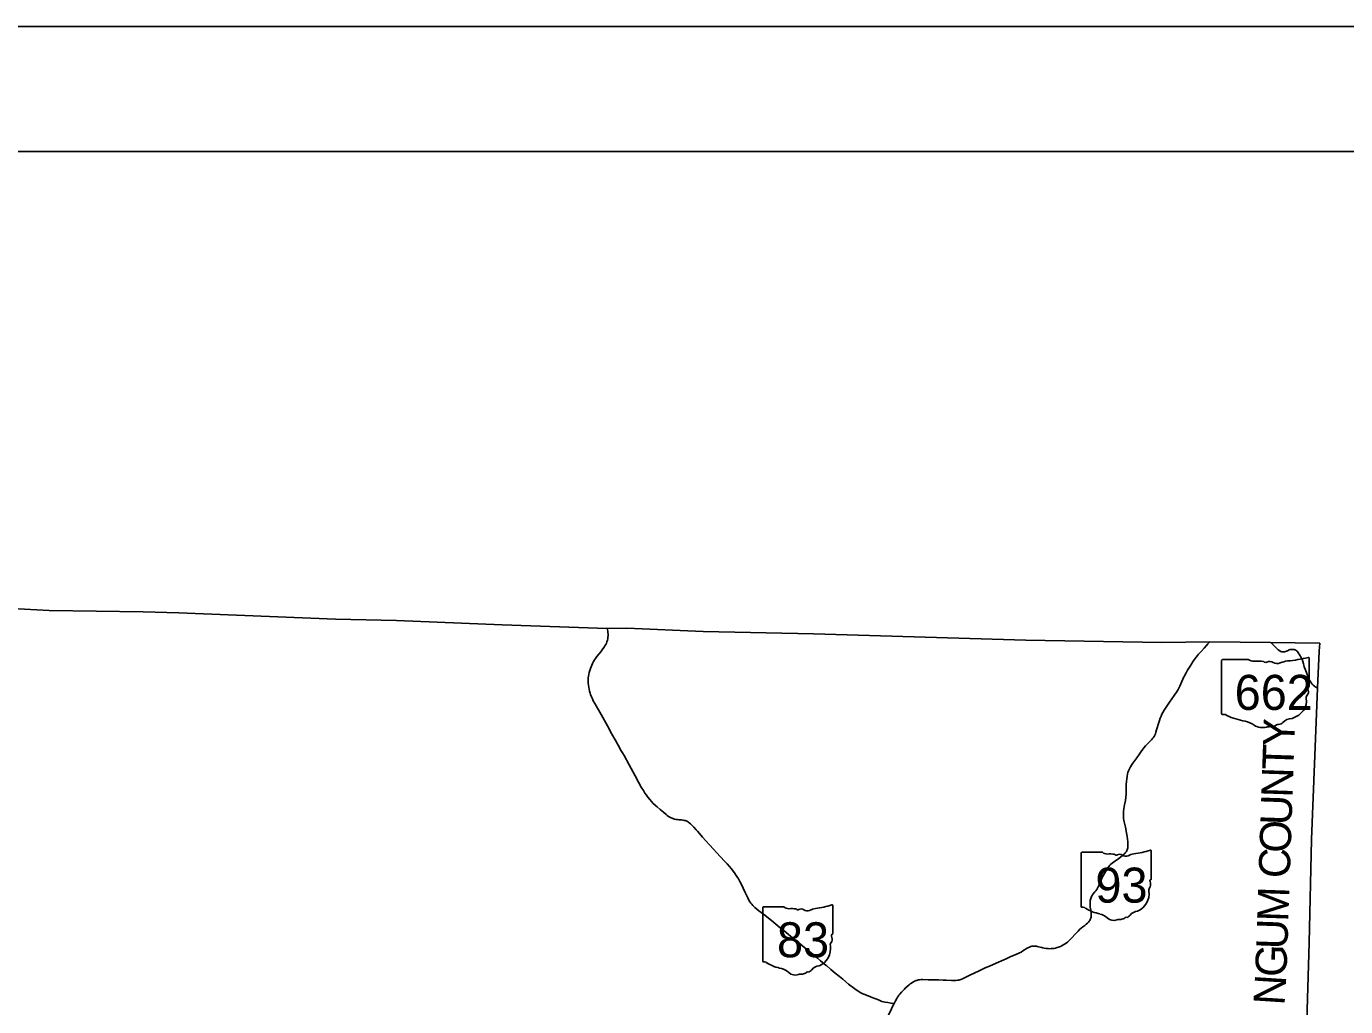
# Model space of a CAD drawing. Extents: x 2015843 to 2287843, y 623733 to 799733.
# Drawn here: x 2161112 to 2203322, y 768366 to 799733 of the extents above; entities that cross this region are included whole.
import ezdxf

# ---------------------------------------------------------------- set-up
doc = ezdxf.new("R2010")
doc.units = 0
for name, color, linetype in [('GM_X_County', 7, 'Continuous'), ('GM_X_County_Text', 7, 'Continuous'), ('GM_X_State_Location', 7, 'Continuous'), ('GM_X_State_Route', 7, 'Continuous'), ('GM_X_State_Shield', 7, 'Continuous'), ('SH_Border', 7, 'Continuous'), ('SH_Cut_Line', 7, 'Continuous')]:
    doc.layers.add(name, color=color, linetype=linetype)

msp = doc.modelspace()

# ---------------------------------------------------------------- linework, layer by layer
at = {"layer": 'GM_X_County'}
msp.add_lwpolyline([(2160255, 781127), (2161838, 781046), (2164851, 780995), (2165985, 780969), (2171000, 780768), (2172957, 780727), (2176338, 780588), (2179692, 780466), (2180329, 780472), (2182770, 780366), (2186293, 780295), (2193090, 780093), (2197442, 780016), (2198976, 780038), (2200924, 780017), (2202494, 779994), (2202479, 779737), (2202424, 778558), (2202231, 773716), (2202153, 770412), (2201913, 762197)], dxfattribs=at)
at = {"layer": 'GM_X_State_Route'}
for points in [[(2188873, 768462), (2188775, 768480), (2188678, 768496), (2188586, 768511), (2188581, 768512), (2188534, 768522), (2188487, 768535), (2188440, 768551), (2188395, 768569), (2188320, 768602), (2188254, 768630), (2188229, 768641), (2188122, 768683), (2187938, 768750), (2187877, 768775), (2187833, 768796), (2187790, 768820), (2187748, 768845), (2187694, 768881), (2187615, 768940), (2187421, 769090), (2187230, 769244), (2187128, 769327), (2186989, 769441), (2186851, 769558), (2186708, 769679), (2186701, 769685), (2186524, 769832), (2186423, 769915), (2186220, 770082), (2186016, 770247), (2185825, 770402), (2185649, 770549), (2185560, 770622), (2185484, 770684), (2185357, 770787), (2185229, 770891), (2185089, 771005), (2184950, 771119), (2184694, 771324), (2184552, 771435), (2184423, 771536), (2184387, 771569), (2184353, 771604), (2184321, 771641), (2184291, 771680), (2184264, 771721), (2184231, 771777), (2184192, 771849), (2184099, 772041), (2184042, 772159), (2183979, 772292), (2183941, 772365), (2183892, 772451), (2183841, 772535), (2183804, 772590), (2183765, 772643), (2183657, 772787), (2183606, 772852), (2183532, 772935), (2183450, 773024), (2183325, 773162), (2183194, 773303), (2183102, 773402), (2182973, 773544), (2182852, 773676), (2182750, 773792), (2182647, 773906), (2182582, 773978), (2182541, 774024), (2182464, 774106), (2182400, 774176), (2182364, 774212), (2182323, 774247), (2182292, 774272), (2182266, 774287), (2182240, 774300), (2182219, 774309), (2182190, 774319), (2182159, 774327), (2182119, 774334), (2182071, 774339), (2181993, 774346), (2181945, 774350), (2181897, 774357), (2181849, 774368), (2181818, 774378), (2181772, 774394), (2181742, 774407), (2181699, 774429), (2181657, 774454), (2181617, 774482), (2181579, 774513), (2181492, 774588), (2181391, 774672), (2181291, 774756), (2181240, 774802), (2181230, 774811), (2181171, 774867), (2181115, 774927), (2181061, 774989), (2181000, 775065), (2180951, 775131), (2180905, 775198), (2180852, 775281), (2180785, 775393), (2180697, 775550), (2180588, 775752), (2180465, 775983), (2180403, 776098), (2180237, 776398), (2180185, 776486), (2180145, 776554), (2180047, 776734), (2179951, 776904), (2179805, 777161), (2179801, 777168), (2179701, 777350), (2179498, 777716), (2179300, 778070), (2179252, 778156), (2179223, 778216), (2179196, 778276), (2179165, 778350), (2179150, 778397), (2179132, 778459), (2179116, 778523), (2179105, 778587), (2179097, 778652), (2179091, 778717), (2179088, 778783), (2179089, 778821), (2179092, 778884), (2179098, 778945), (2179107, 778994), (2179121, 779057), (2179138, 779121), (2179158, 779183), (2179181, 779244), (2179200, 779289), (2179229, 779348), (2179260, 779406), (2179293, 779462), (2179320, 779503), (2179368, 779569), (2179490, 779723), (2179560, 779814), (2179598, 779868), (2179625, 779909), (2179650, 779952), (2179671, 779997), (2179689, 780043), (2179702, 780091), (2179712, 780139), (2179719, 780188), (2179722, 780238), (2179722, 780287), (2179718, 780336), (2179714, 780382), (2179707, 780418), (2179693, 780463)], [(2188873, 768462), (2188923, 768551), (2188962, 768623), (2188986, 768666), (2189012, 768708), (2189031, 768735), (2189048, 768758), (2189056, 768767), (2189117, 768834), (2189184, 768906), (2189203, 768925), (2189231, 768953), (2189291, 769009), (2189353, 769063), (2189392, 769094), (2189432, 769122), (2189474, 769148), (2189517, 769173), (2189547, 769187), (2189578, 769199), (2189602, 769207), (2189625, 769214), (2189657, 769221), (2189690, 769226), (2189739, 769230), (2189789, 769231), (2189969, 769227), (2190117, 769224), (2190232, 769223), (2190298, 769222), (2190445, 769215), (2190543, 769211), (2190707, 769205), (2190805, 769203), (2190854, 769205), (2190903, 769209), (2190951, 769216), (2190983, 769224), (2191014, 769234), (2191059, 769252), (2191133, 769287), (2191294, 769369), (2191456, 769448), (2191575, 769503), (2191768, 769593), (2191949, 769672), (2192219, 769791), (2192309, 769831), (2192459, 769898), (2192482, 769908), (2192593, 769958), (2192774, 770037), (2192849, 770070), (2192893, 770090), (2192936, 770113), (2192993, 770146), (2193132, 770233), (2193176, 770258), (2193203, 770270), (2193226, 770279), (2193253, 770289), (2193284, 770296), (2193313, 770301), (2193331, 770303), (2193351, 770304), (2193385, 770304), (2193411, 770302), (2193432, 770299), (2193454, 770295), (2193499, 770283), (2193600, 770254), (2193630, 770248), (2193677, 770237), (2193737, 770228), (2193802, 770222), (2193851, 770220), (2193905, 770221), (2193946, 770223), (2193997, 770230), (2194044, 770240), (2194092, 770253), (2194138, 770269), (2194198, 770294), (2194242, 770314), (2194285, 770339), (2194331, 770367), (2194381, 770400), (2194419, 770430), (2194456, 770462), (2194492, 770495), (2194550, 770554), (2194682, 770700), (2194761, 770783), (2194820, 770840), (2194858, 770873), (2194909, 770914), (2194974, 770964), (2195021, 771004), (2195060, 771038), (2195092, 771071), (2195116, 771099), (2195134, 771123), (2195151, 771151), (2195162, 771175), (2195169, 771195), (2195179, 771226), (2195183, 771257), (2195185, 771286), (2195185, 771310), (2195183, 771342), (2195179, 771378), (2195166, 771453), (2195152, 771550), (2195148, 771599), (2195145, 771664), (2195147, 771713), (2195153, 771763), (2195159, 771795), (2195168, 771827), (2195179, 771858), (2195192, 771888), (2195208, 771917), (2195227, 771946), (2195248, 771974), (2195298, 772037), (2195328, 772074), (2195357, 772114), (2195383, 772156), (2195405, 772199), (2195425, 772244), (2195461, 772335), (2195485, 772392), (2195508, 772441), (2195537, 772499), (2195577, 772571), (2195682, 772757), (2195706, 772799), (2195724, 772826), (2195745, 772853), (2195777, 772890), (2195812, 772924), (2195852, 772957), (2195932, 773014), (2196064, 773111), (2196184, 773198), (2196220, 773229), (2196245, 773252), (2196267, 773275), (2196283, 773293), (2196293, 773307), (2196306, 773328), (2196320, 773357), (2196332, 773386), (2196342, 773417), (2196349, 773449), (2196353, 773481), (2196356, 773529), (2196356, 773578), (2196353, 773644), (2196345, 773725), (2196333, 773805), (2196316, 773913), (2196302, 773993), (2196277, 774105), (2196232, 774283), (2196224, 774330), (2196217, 774379), (2196212, 774429), (2196212, 774480), (2196212, 774543), (2196217, 774611), (2196230, 774692), (2196252, 774821), (2196278, 774966), (2196283, 775000), (2196287, 775030), (2196294, 775089), (2196298, 775146), (2196300, 775225), (2196305, 775469), (2196314, 775569), (2196322, 775650), (2196330, 775725), (2196346, 775816), (2196359, 775862), (2196372, 775910), (2196392, 775956), (2196414, 776001), (2196439, 776044), (2196469, 776090), (2196514, 776152), (2196640, 776323), (2196716, 776430), (2196781, 776525), (2196838, 776605), (2196877, 776658), (2196919, 776708), (2196953, 776744), (2197036, 776827), (2197083, 776871), (2197116, 776907), (2197136, 776932), (2197165, 776971), (2197192, 777013), (2197215, 777057), (2197235, 777100), (2197252, 777145), (2197276, 777224), (2197345, 777460), (2197366, 777523), (2197393, 777600), (2197416, 777660), (2197445, 777722), (2197474, 777779), (2197517, 777850), (2197562, 777921), (2197690, 778111), (2197839, 778325), (2197930, 778461), (2197964, 778517), (2197989, 778560), (2198016, 778618), (2198050, 778694), (2198083, 778769), (2198116, 778844), (2198149, 778917), (2198173, 778966), (2198188, 778994), (2198219, 779048), (2198264, 779128), (2198344, 779259), (2198397, 779344), (2198423, 779385), (2198477, 779466), (2198535, 779546), (2198578, 779599), (2198619, 779649), (2198696, 779732), (2198797, 779841), (2198871, 779924), (2198917, 779974), (2198977, 780035)], [(2202425, 778555), (2202388, 778576), (2202348, 778603), (2202322, 778624), (2202285, 778656), (2202255, 778689), (2202223, 778728), (2202194, 778766), (2202168, 778808), (2202147, 778848), (2202128, 778893), (2202066, 779059), (2202028, 779163), (2202000, 779241), (2201985, 779292), (2201974, 779337), (2201955, 779413), (2201947, 779441), (2201939, 779461), (2201924, 779492), (2201909, 779521), (2201835, 779648), (2201809, 779689), (2201790, 779716), (2201779, 779729), (2201767, 779741), (2201755, 779752), (2201742, 779762), (2201727, 779771), (2201713, 779778), (2201697, 779785), (2201681, 779790), (2201665, 779794), (2201649, 779797), (2201633, 779798), (2201614, 779799), (2201599, 779798), (2201583, 779797), (2201567, 779795), (2201544, 779789), (2201517, 779781), (2201458, 779756), (2201427, 779743), (2201396, 779731), (2201368, 779724), (2201351, 779720), (2201336, 779718), (2201320, 779717), (2201304, 779718), (2201288, 779720), (2201273, 779723), (2201258, 779728), (2201244, 779733), (2201230, 779740), (2201215, 779748), (2201199, 779758), (2201180, 779774), (2201163, 779787), (2200925, 780014)], [(2188669, 768052), (2188682, 768076), (2188793, 768292), (2188847, 768408), (2188873, 768462)]]:
    msp.add_lwpolyline(points, dxfattribs=at)
at = {"layer": 'GM_X_State_Shield'}
for p, q in [((2199356, 779442), (2199356, 777741)), ((2200204, 779471), (2199383, 779471)), ((2202158, 778624), (2202158, 779514)), ((2202157, 778624), (2202158, 778624)), ((2195539, 773304), (2194883, 773304)), ((2197102, 772456), (2197102, 773346)), ((2194861, 773275), (2194861, 771573)), ((2197102, 772456), (2197102, 772456)), ((2186914, 770707), (2186914, 771597)), ((2184672, 771526), (2184672, 769824)), ((2185351, 771555), (2184694, 771555)), ((2186913, 770707), (2186914, 770707))]:
    msp.add_line(p, q, dxfattribs=at)
for centre, radius, start, end in [((2194887, 773278), 26, 98.1301, 188.1301), ((2195696, 773501), 252, 231.6195, 271.1119), ((2196304, 775623), 2377, 275.8445, 288.9065), ((2197077, 773350), 25, 351.8621, 97.738), ((2195779, 772349), 904, 80.4867, 94.9883), ((2195985, 773287), 72.7, 219.7921, 297.1024), ((2196091, 773090), 151, 54.4667, 119.1411), ((2196286, 773360), 182, 233.8562, 294.8282), ((2196607, 772784), 478, 97.3462, 120.7689), ((2197076, 772453), 26.7, 289.6038, 7.7341), ((2196437, 771971), 595, 292.3089, 8.9858), ((2197192, 772084), 169, 136.8065, 186.9296), ((2197097, 772391), 38.6, 107.944, 210.337), ((2196851, 772278), 232, 340.033, 23.6496), ((2186115, 773874), 2377, 275.8445, 288.9065), ((2186889, 771601), 25, 351.8621, 97.738), ((2184698, 771529), 26, 98.1301, 188.1301), ((2185507, 771752), 252, 231.6195, 271.1119), ((2185590, 770600), 904, 80.4867, 94.9883), ((2185796, 771538), 72.7, 219.7921, 297.1024), ((2185902, 771341), 151, 54.4667, 119.1411), ((2186097, 771611), 182, 233.8562, 294.8282), ((2186418, 771035), 478, 97.3462, 120.7689), ((2194887, 771570), 26.2, 171.9584, 258.3066), ((2194891, 771744), 200, 267.339, 280.6039), ((2194932, 771475), 72.1, 29.7484, 93.2717), ((2195842, 773004), 1716, 240.4129, 257.1985), ((2195330, 770809), 537, 47.1842, 75.836), ((2195911, 771467), 341, 230.7004, 286.2918), ((2196133, 771339), 182, 268.777, 315.5493), ((2196297, 771175), 51.1, 65.7517, 132.6484), ((2196275, 771409), 192, 282.8732, 323.2771), ((2196688, 771096), 326, 94.4031, 142.5768), ((2196108, 770879), 280, 85.6951, 111.2099), ((2187003, 770335), 169, 136.8065, 186.9296), ((2186908, 770642), 38.6, 107.944, 210.337), ((2186662, 770529), 232, 340.033, 23.6496), ((2186887, 770704), 26.7, 289.6038, 7.7341), ((2186248, 770222), 595, 292.3089, 8.9858), ((2184698, 769821), 26.2, 171.9584, 258.3066), ((2184702, 769995), 200, 267.339, 280.6039), ((2184743, 769726), 72.1, 29.7484, 93.2717), ((2185653, 771255), 1716, 240.4129, 257.1985), ((2185141, 769060), 537, 47.1842, 75.836), ((2186086, 769660), 192, 282.8732, 323.2771), ((2186499, 769347), 326, 94.4031, 142.5768), ((2185722, 769718), 341, 230.7004, 286.2918), ((2185919, 769130), 280, 85.6951, 111.2099), ((2185944, 769590), 182, 268.777, 315.5493), ((2186108, 769426), 51.1, 65.7517, 132.6484)]:
    msp.add_arc(centre, radius, start, end, dxfattribs=at)
for centre, major_axis, start_param, end_param in [((2199388, 779446), (32.5, 0), 1.712693, 3.28349), ((2200399, 779669), (315, 0), 4.042523, 4.731795), ((2200504, 778516), (1130, 0), 1.404758, 1.657858), ((2200760, 779455), (90.8, 0), 3.836095, 5.185415), ((2200894, 779258), (189, 0), 0.950623, 2.079405), ((2201137, 779528), (227, 0), 4.081561, 5.145723), ((2201539, 778952), (598, 0), 1.699011, 2.107814), ((2201160, 781791), (2971, 0), 4.814394, 5.042369), ((2202126, 779517), (31.2, 0), 6.141152, 7.989035), ((2202269, 778251), (211, 0), 2.387724, 3.262537), ((2202150, 778558), (48.3, 0), 1.883978, 3.671073), ((2201843, 778446), (290, 0), 5.934695, 6.695948), ((2202124, 778620), (33.4, 0), 5.05454, 6.418171), ((2201326, 778138), (743, 0), 5.101752, 6.440018), ((2199388, 777737), (32.7, 0), 3.00124, 4.508301), ((2199393, 777911), (250, 0), 4.665946, 4.897461), ((2199444, 777643), (90.1, 0), 0.519207, 1.627899), ((2200582, 779171), (2146, 0), 4.195997, 4.488961), ((2201639, 777263), (407, 0), 1.647645, 2.488434), ((2199942, 776977), (671, 0), 0.823519, 1.323587), ((2200668, 777634), (426, 0), 4.026481, 4.996735), ((2200914, 777046), (350, 0), 1.495662, 1.94098), ((2200946, 777507), (227, 0), 4.691044, 5.507374), ((2201151, 777342), (63.9, 0), 1.147584, 2.315152), ((2201124, 777576), (240, 0), 4.937069, 5.64225)]:
    msp.add_ellipse(centre, major_axis=major_axis, ratio=0.8, start_param=start_param, end_param=end_param, dxfattribs=at)
at = {"layer": 'SH_Border'}
msp.add_lwpolyline([(2027843, 795733), (2283843, 795733), (2283843, 627733), (2027843, 627733)], close=True, dxfattribs=at)
at = {"layer": 'SH_Cut_Line'}
msp.add_lwpolyline([(2015843, 623733), (2287843, 623733), (2287843, 799733), (2015843, 799733)], close=True, dxfattribs=at)

# ---------------------------------------------------------------- texts
at = {"layer": 'GM_X_County_Text'}
for s, rotation, p in [('Y', 88.0661, (2201677, 776676)), ('T', 88.0634, (2201651, 775929)), ('N', 88.0649, (2201622, 775045)), ('U', 88.0662, (2201592, 774161)), ('O', 88.0655, (2201562, 773277)), ('C', 88.0644, (2201534, 772464)), ('M', 88.0647, (2201487, 771074)), ('U', 88.0562, (2201458, 770190)), ('G', 87.8269, (2201424, 769302)), ('N', 86.3351, (2201366, 768391))]:
    msp.add_text(s, height=1000, rotation=rotation, dxfattribs=at).set_placement(p)
at = {"layer": 'GM_X_State_Location'}
for s, p in [('662', (2201529, 779376)), ('93', (2195290, 772314)), ('83', (2185526, 770255))]:
    msp.add_text(s, height=1, rotation=0, dxfattribs=at).set_placement(p)
for s, p in [('s', (2201882, 779449)), ('r', (2201882, 779449)), ('s', (2195541, 772387)), ('r', (2195541, 772387)), ('s', (2185778, 770328)), ('r', (2185778, 770328))]:
    msp.add_text(s, height=1, dxfattribs=at).set_placement(p)
at = {"layer": 'GM_X_State_Shield'}
for s, p in [('662', (2199772, 777861)), ('93', (2195317, 771693)), ('83', (2185128, 769944))]:
    msp.add_text(s, height=1120.7, dxfattribs=at).set_placement(p)

doc.saveas('drawing.dxf')
